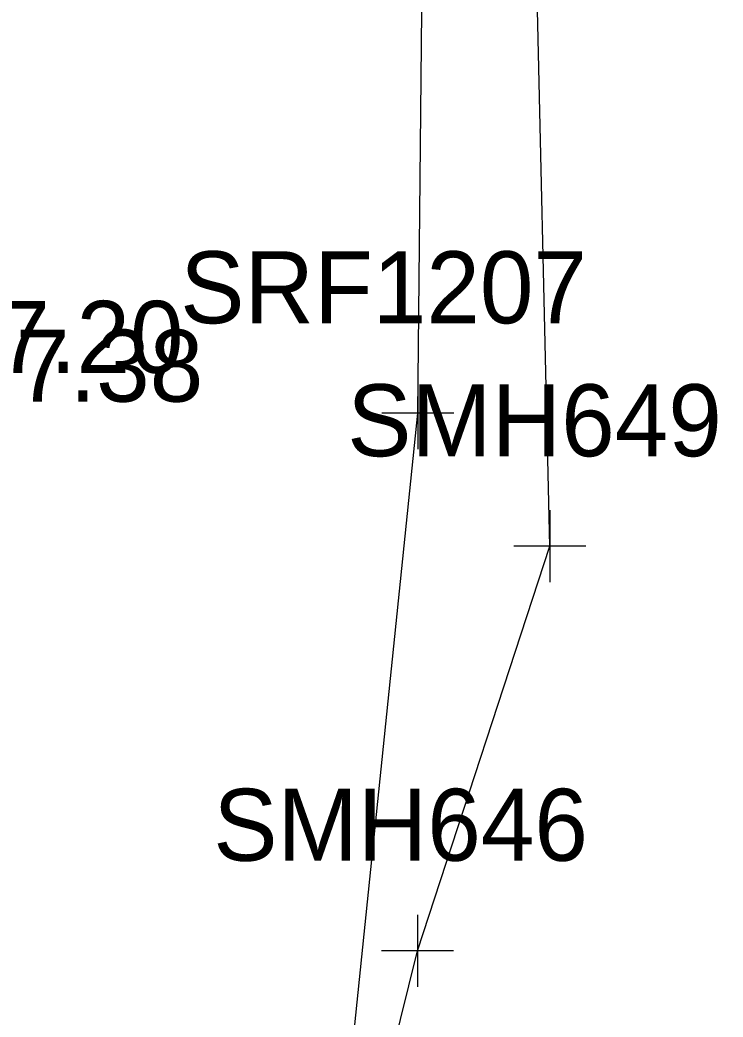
# Model space of a CAD drawing. Extents: x 941041 to 969446, y 397014 to 416764.
# Drawn here: x 951897.6 to 951936.7, y 403078.9 to 403134.3 of the extents above; entities that cross this region are included whole.
import ezdxf

# ---------------------------------------------------------------- set-up
doc = ezdxf.new("R2010")
doc.units = 0
for name, color, linetype in [('SURVEY - DTM - Breaklines', 7, 'Continuous'), ('SURVEY - DTM - Breaklines - Points - Elevations', 7, 'Continuous'), ('SURVEY - DTM - Breaklines - Points - Locators', 7, 'Continuous'), ('SURVEY - DTM - Breaklines - Points - Numbers', 7, 'Continuous'), ('SURVEY - UTILITIES - Telephone (Underground) - Points - Locators', 7, 'Continuous'), ('SURVEY - UTILITIES - Telephone (Underground) - Points - Numbers', 7, 'Continuous'), ('SURVEY - UTILITIES - Telephone (Underground) with Text', 7, 'Continuous')]:
    doc.layers.add(name, color=color, linetype=linetype)

msp = doc.modelspace()

# ---------------------------------------------------------------- linework, layer by layer
at = {"layer": 'SURVEY - DTM - Breaklines'}
msp.add_lwpolyline([(952284.319, 403445.189), (952160.86, 403236.955), (952125.869, 403192.452), (952077.942, 403136.622), (952039.185, 403098.254), (952006.25, 403068.239), (951969.461, 403038.091), (951934.259, 403008.176), (951912.189, 402997.336), (951900.803, 403002.026), (951909.306, 403040.458), (951919.737, 403082.568), (951927.082, 403105.038), (951926.24, 403141.28), (951910.025, 403171.308), (951930.399, 403184.139)], dxfattribs=at)
at = {"layer": 'SURVEY - DTM - Breaklines - Points - Locators'}
for p, q in [((951927.082, 403107.038), (951927.082, 403103.038)), ((951929.082, 403105.038), (951925.082, 403105.038)), ((951919.737, 403084.568), (951919.737, 403080.568)), ((951921.737, 403082.568), (951917.737, 403082.568))]:
    msp.add_line(p, q, dxfattribs=at)
at = {"layer": 'SURVEY - UTILITIES - Telephone (Underground) - Points - Locators'}
for p, q in [((951919.741, 403114.424), (951919.741, 403110.424)), ((951921.741, 403112.424), (951917.741, 403112.424))]:
    msp.add_line(p, q, dxfattribs=at)
at = {"layer": 'SURVEY - UTILITIES - Telephone (Underground) with Text'}
msp.add_lwpolyline([(951904.603, 402973.169), (951905.577, 402979.767), (951910.846, 402997.186), (951914.788, 403064.244), (951919.741, 403112.424), (951920.389, 403177.557), (951921.214, 403191.192), (951922.129, 403203.906), (951922.407, 403213.171), (951921.072, 403252.511), (951917.249, 403313.567)], dxfattribs=at)

# ---------------------------------------------------------------- texts
at = {"layer": 'SURVEY - DTM - Breaklines - Points - Elevations'}
for s, p in [('EL-367.20', (951882.051, 403114.67)), ('EL-367.38', (951883.144, 403113.072))]:
    msp.add_text(s, height=4, dxfattribs=at).set_placement(p)
at = {"layer": 'SURVEY - DTM - Breaklines - Points - Numbers'}
for s, p in [('SMH649', (951915.827, 403110.038)), ('SMH646', (951908.387, 403087.568))]:
    msp.add_text(s, height=4, dxfattribs=at).set_placement(p)
at = {"layer": 'SURVEY - UTILITIES - Telephone (Underground) - Points - Numbers'}
msp.add_text('SRF1207', height=4, dxfattribs=at).set_placement((951906.549, 403117.424))

doc.saveas('drawing.dxf')
